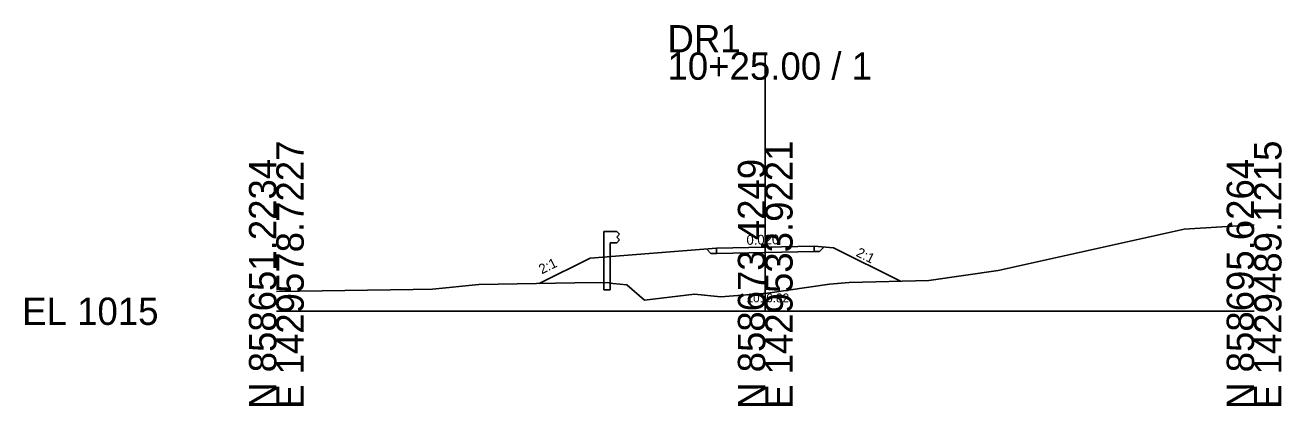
# Model space of a CAD drawing. Extents: x -26 to 103, y -10 to 1022.
# Drawn here: x -25.7 to 102.8, y -9.7 to 29.3 of the extents above; entities that cross this region are included whole.
import ezdxf

# ---------------------------------------------------------------- set-up
doc = ezdxf.new("R2010")
doc.units = 0
for name, color, linetype in [('Exist Cross Section Cell', 7, 'Continuous'), ('Exist XS Center Line Elevation Label', 7, 'Continuous'), ('Exist XS Ground Line', 7, 'Continuous'), ('Prop CMT Guardrail Graphics', 7, 'Continuous'), ('Prop CMT Pvmt Surface', 7, 'Continuous'), ('Prop CMT Shld Paved Course 1', 7, 'Continuous'), ('Prop CMT Slope Grass', 7, 'Continuous'), ('Prop CMT Subgrade Earthwork', 7, 'Continuous'), ('Prop CMT Template Flag', 7, 'Continuous'), ('Prop XS SE Text', 7, 'Continuous'), ('Prop XS Side Slope Text', 7, 'Continuous')]:
    doc.layers.add(name, color=color, linetype=linetype)

msp = doc.modelspace()

# ---------------------------------------------------------------- linework, layer by layer
at = {"layer": 'Exist Cross Section Cell'}
for p, q in [((50, 0), (50, 26.51)), ((0, 0), (50, 0)), ((50, 0), (100, 0))]:
    msp.add_line(p, q, dxfattribs=at)
at = {"layer": 'Exist XS Ground Line'}
msp.add_lwpolyline([(0, 2.01), (13.98, 2.23), (15.98, 2.27), (20.71, 2.73), (30.54, 2.9), (33.88, 2.94), (34.41, 2.86), (35.83, 2.72), (37.65, 1.15), (42.76, 1.76), (45.46, 1.48), (50.24, 1.84), (56.57, 2.77), (58.6, 2.96), (66.75, 3.16), (73.84, 4.18), (92.85, 8.4), (100, 8.84)], dxfattribs=at)
at = {"layer": 'Prop CMT Guardrail Graphics'}
for points in [[(33.48, 2.18), (33.48, 8.18)], [(33.48, 8.18), (34.81, 8.18), (35.08, 7.88)], [(35.08, 7.88), (34.81, 7.59)], [(35.08, 7.3), (34.81, 7.01), (34.15, 7.01)], [(34.15, 7.01), (34.15, 2.18)], [(34.81, 7.59), (35.08, 7.3)], [(34.15, 2.18), (33.48, 2.18)]]:
    msp.add_lwpolyline(points, dxfattribs=at)
at = {"layer": 'Prop CMT Pvmt Surface'}
msp.add_line((50, 6.57), (45, 6.47), dxfattribs=at)
msp.add_lwpolyline([(55, 6.67), (50, 6.57)], dxfattribs=at)
at = {"layer": 'Prop CMT Shld Paved Course 1'}
for points in [[(45, 5.93), (45, 6.47)], [(55, 6.13), (55, 6.67)]]:
    msp.add_lwpolyline(points, dxfattribs=at)
at = {"layer": 'Prop CMT Slope Grass'}
for p, q in [((45, 6.47), (32.08, 5.44)), ((55, 6.67), (57, 6.51)), ((63.84, 3.09), (57, 6.51)), ((32.08, 5.44), (26.88, 2.83))]:
    msp.add_line(p, q, dxfattribs=at)
at = {"layer": 'Prop CMT Subgrade Earthwork'}
for points in [[(55.55, 6.12), (56.02, 6.59)], [(44.45, 5.92), (43.98, 6.39)], [(45, 5.93), (44.45, 5.92)], [(55, 6.13), (55.55, 6.12)]]:
    msp.add_lwpolyline(points, dxfattribs=at)
at = {"layer": 'Prop CMT Template Flag'}
msp.add_line((45, 5.93), (50, 6.03), dxfattribs=at)
msp.add_lwpolyline([(50, 6.03), (55, 6.13)], dxfattribs=at)

# ---------------------------------------------------------------- texts
at = {"layer": 'Exist Cross Section Cell'}
for s, p in [('DR1', (40, 26.51)), ('10+25.00 / 1', (40, 23.71)), ('EL 1015', (-26, -1.4))]:
    msp.add_text(s, height=2.8, dxfattribs=at).set_placement(p)
for s, p in [('E 1429578.7227', (2.8, -10)), ('E 1429533.9221', (52.8, -10)), ('E 1429489.1215', (102.8, -10)), ('N 858651.2234', (0, -10)), ('N 858673.4249', (50, -10)), ('N 858695.6264', (100, -10))]:
    msp.add_text(s, height=2.8, rotation=90, dxfattribs=at).set_placement(p)
at = {"layer": 'Exist XS Center Line Elevation Label'}
msp.add_text('1016.82', height=0.9, dxfattribs=at).set_placement((48.09, 0.92))
at = {"layer": 'Prop XS SE Text'}
msp.add_text('0.020', height=1, rotation=1.1458, dxfattribs=at).set_placement((48.09, 6.8))
at = {"layer": 'Prop XS Side Slope Text'}
for rotation, p in [(333.4349, (59.21, 5.69)), (26.5651, (27.15, 3.78))]:
    msp.add_text('2:1', height=1, rotation=rotation, dxfattribs=at).set_placement(p)

doc.saveas('drawing.dxf')
